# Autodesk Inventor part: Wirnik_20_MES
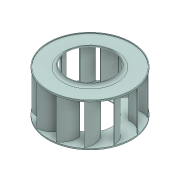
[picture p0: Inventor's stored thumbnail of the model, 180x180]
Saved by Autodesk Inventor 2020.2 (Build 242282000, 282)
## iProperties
Created: 2017-03
Part Number: Wirnik_20_MES
Material: Stal
Document SubType Name: Modeling
Designer: F.Stasiak
Density: 7.85 g/cm^3
Appearance: Stal
Catalog Web Link: www.expertbooks.pl
Manager: www.cadconsulting.pl
Company: Fabian Stasiak CAD Consulting
Author: F.Stasiak
Subject: Zbiór ćwiczeń. Autodesk Inventor 2020. Kurs Professional
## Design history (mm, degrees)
sketch "Szkic3"
  geometry: C1 r 125 at (0, 0); C2 r 65 at (0, 0); 1 further point
  constraints: 2 centre point, 2 coincident
  dimensions: "d4" = 250 diameter of C1; "d5" = 130 diameter of C2
extrude "Wyciągnięcie proste3" new body sketch "Szkic3" distance "d6" = 2 (= GRUBOŚĆ); taper "d7" = 0 deg
sketch "Szkic4" dims "d8" = 170
  geometry: L1 (0, 85)-(42.816, 114.98); L2 (-175, 0)-(175, 0) reference; C1 r 65 at (0, 0) reference; C2 r 125 at (0, 0) reference; A1 r 50 centre (45.857, 65.073) between (42.816, 114.98) and (0, 85); 2 further points
  constraints: 2 end point, 2 point on circle, 2 vertical alignment, 1 centre point, 1 coincident, 2 other
  dimensions: "d9" = 50 radius of A1; "d27" = 55 dimension on A1; "d28" = 35 deg angle of L1 L2
  node "Pętla rzutowana1"
sketch "Szkic5"
  geometry: L1 (125, 122)-(80, 122); L2 (125, 124)-(80, 124); L3 (68.214, 131.742)-(70.258, 131.742); L4 (125, 122)-(125, 124); L5 (125, 2)-(-125, 2) reference; L6 (0, -14.2)-(0, 85.2) reference; A1 r 12 centre (80, 134) between (68.214, 131.742) and (80, 122); A2 r 10 centre (80, 134) between (70.258, 131.742) and (80, 124); 1 further point
  constraints: 8 end point, 4 point on circle, 2 centre point, 2 horizontal, 1 tangent, 1 vertical, 1 vertical alignment, 1 other
  dimensions: "d11" = 2 distance between parallel lines of L2 L1 (= GRUBOŚĆ); "d12" = 45 distance from line of A1.centre L4; "d13" = 10 radius of A2; "d14" = 120 distance between parallel lines of L1 L5
revolve "Obrót1" sketch "Szkic5" stored, may be unused: angle "d15" = 90 deg
sketch "Szkic6"
  geometry: C1 r 65 at (0, 0) reference; C2 r 125 at (0, 0) reference; C3 r 123 at (0, 0); 1 further point
  constraints: 1 centre point
  dimensions: "d18" = 2 radial gap between concentric circles of C2 C3 (= GRUBOŚĆ)
extrude "Wyciągnięcie proste5" join sketch "Szkic6" distance "d19" = 2 (= GRUBOŚĆ); taper "d20" = 0 deg
sketch "Szkic7"
  geometry: C1 r 125 at (0, 0) reference; C2 r 123 at (0, 0); 1 further point
  constraints: 1 centre point
  dimensions: "d21" = 2 radial gap between concentric circles of C1 C2 (= GRUBOŚĆ)
extrude "Wyciągnięcie proste6" join sketch "Szkic7" distance "d22" = 2 (= GRUBOŚĆ); taper "d23" = 0 deg
feature "PowWyciągnięciaProstego1" dims "d29" = 0, "d30" = 0
feature "Pogrubienie1" dims "d31" = 2 (= GRUBOŚĆ), "d32" = 2 (= GRUBOŚĆ)
pattern_circular "Szyk kołowy2" dims angle "d34" = 360 deg
node "Bryła3"
node "Pętla rzutowana2"
body "Srf1"
body "Srf2"
body "Srf3"
body "Srf4"
body "Srf5"
body "Srf6"
body "Srf7"
body "Srf8"
body "Srf9"
body "Srf10"
body "Srf11"
body "Srf12"
feature "PowWyciągnięciaProstego2"
feature "PowWyciągnięciaProstego3"
feature "PowWyciągnięciaProstego4"
feature "PowWyciągnięciaProstego5"
feature "PowWyciągnięciaProstego6"
feature "PowWyciągnięciaProstego7"
feature "PowWyciągnięciaProstego8"
feature "PowWyciągnięciaProstego9"
feature "PowWyciągnięciaProstego10"
feature "PowWyciągnięciaProstego11"
feature "PowWyciągnięciaProstego12"
other parameters: "GRUBOŚĆ" = 2 [user parameter; used in 8 equation terms]
